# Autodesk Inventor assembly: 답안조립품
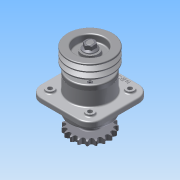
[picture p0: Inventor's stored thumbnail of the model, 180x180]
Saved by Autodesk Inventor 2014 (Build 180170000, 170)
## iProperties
Created: 2015-09
Part Number: 답안조립품
Document SubType Name: Assembly
Designer: study
Author: study
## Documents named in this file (12)
- C:\Users\study\Desktop\450909v1013\답안조립품.iam
- C:\Users\study\Desktop\450909v1013\본체.ipt
- C:\Users\study\Desktop\450909v1013\3-축.ipt
- C:\Users\study\Desktop\450909v1013\7-부시.ipt
- C:\Users\study\Desktop\450909v1013\6-베어링 6206.ipt
- C:\Users\study\Desktop\450909v1013\2-커버.ipt
- C:\Users\study\Desktop\450909v1013\10-M6.ipt
- C:\Users\study\Desktop\450909v1013\8-오일실 30x42.ipt
- C:\Users\study\Desktop\450909v1013\11-키 6x6.ipt
- C:\Users\study\Desktop\450909v1013\4-V벨트풀리.ipt
- C:\Users\study\Desktop\450909v1013\5-체인 스프로킷.ipt
- C:\Users\study\Desktop\450909v1013\9-M16-너트.ipt
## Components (22 placed, 10 different names)
1. 3-축:1 — 각도:1, 각도:2
2. 7-부시:1
3. 6-베어링 6206:1
4. 6-베어링 6206:2
5. 2-커버:1
6. 2-커버:2
7. 8-8-오일실 30x42:1
8. 8-8-오일실 30x42:2
9. 11-키 6x6:1 — 각도:1, 각도:3
10. 11-키 6x6:2 — 각도:2, 각도:4
11. 4-V벨트풀리:1 — 각도:3
12. 5-체인 스프로킷:1 — 각도:4
13. 9-M16 너트:1
14. 9-M16 너트:2
15. 10-M6:5
16. 10-M6:6
17. 10-M6:7
18. 10-M6:8
19. 10-M6:9
20. 10-M6:10
21. 10-M6:11
22. 10-M6:12
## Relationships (4: Angle 4)
- 각도:1 [Angle]: 3-축:1 ↔ 11-키 6x6:1
- 각도:2 [Angle]: 3-축:1 ↔ 11-키 6x6:2
- 각도:3 [Angle]: 11-키 6x6:1 ↔ 4-V벨트풀리:1
- 각도:4 [Angle]: 11-키 6x6:2 ↔ 5-체인 스프로킷:1
